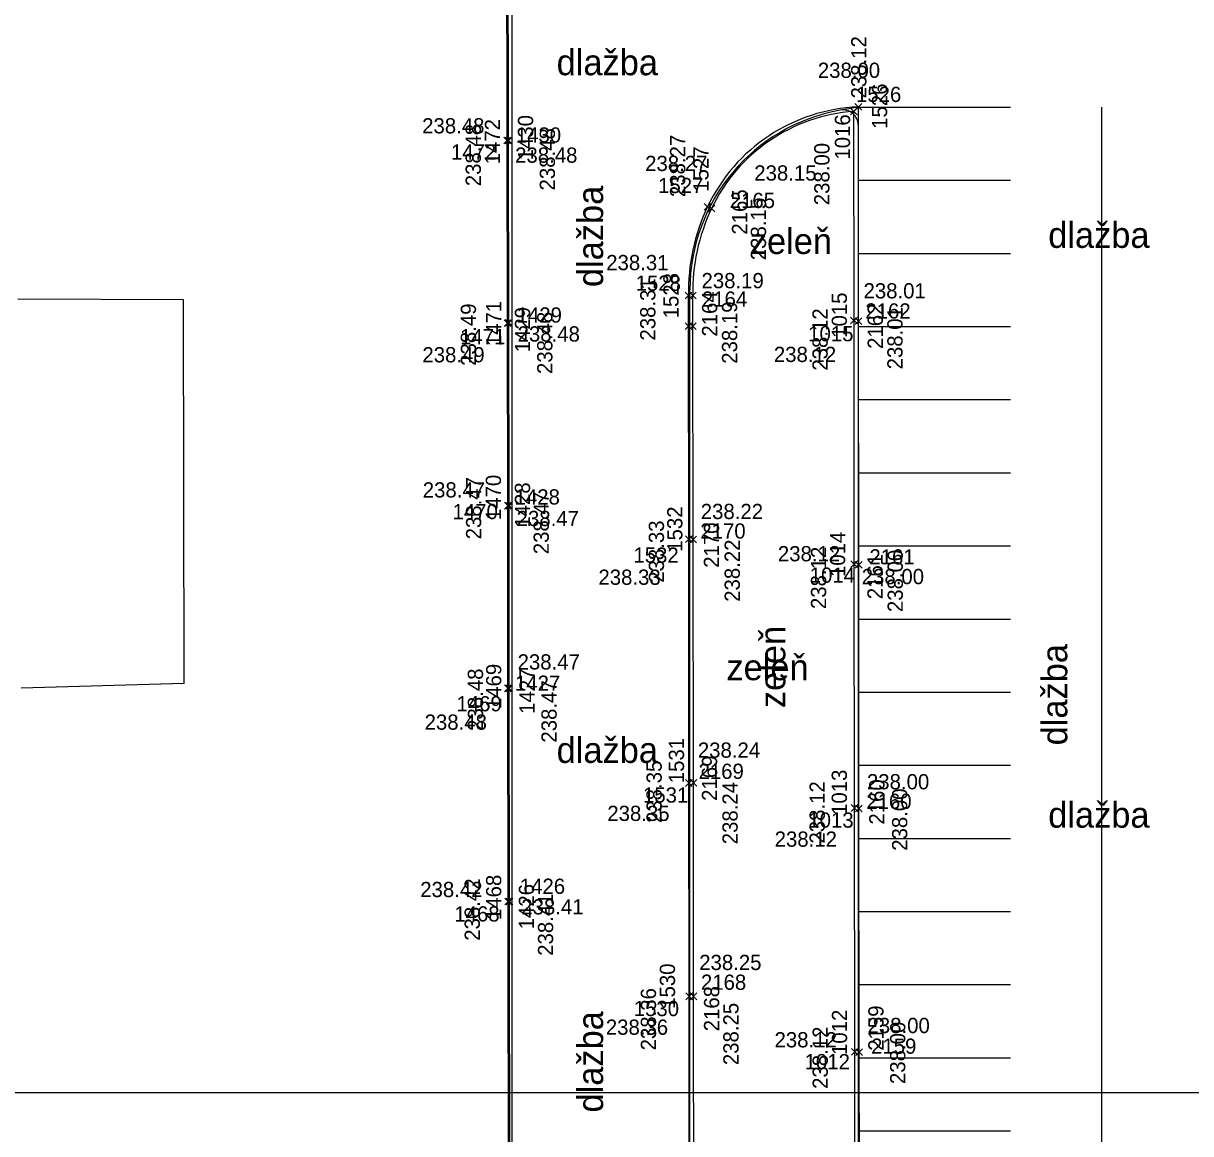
# Model space of a CAD drawing. Extents: x -264205 to -263659, y -1242401 to -1241986.
# Drawn here: x -263975.5 to -263937.18, y -1242121 to -1242084.56 of the extents above; entities that cross this region are included whole.
import ezdxf

# ---------------------------------------------------------------- set-up
doc = ezdxf.new("R2010")
doc.units = 0
for name, color, linetype in [('BOD_CISLO_2-2', 7, 'Continuous'), ('BOD_CISLO_2-3', 7, 'Continuous'), ('BOD_SYMBOL_2-2', 7, 'Continuous'), ('BOD_SYMBOL_2-3', 7, 'Continuous'), ('BOD_VYSKA_2-2', 7, 'Continuous'), ('BOD_VYSKA_2-3', 7, 'Continuous'), ('POPIS_2-2', 7, 'Continuous'), ('POPIS_2-3', 7, 'Continuous'), ('PROJEKT_OBRUBNIKY_KOMUNIKACIE', 7, 'Continuous'), ('PROJEKT_TDZ_VODOROVNE', 7, 'Continuous'), ('RAM_NA_TLAC_2-2_1-250', 7, 'Continuous'), ('SITUACIA_DSP_2D', 7, 'Continuous'), ('SO_20-4_OBRUBNIKY_DOLNA_HRANA', 7, 'Continuous'), ('SO_20-4_OBRUBNIKY_HORNA_HRANA', 7, 'Continuous')]:
    doc.layers.add(name, color=color, linetype=linetype)

msp = doc.modelspace()

# ---------------------------------------------------------------- linework, layer by layer
at = {"layer": 'BOD_SYMBOL_2-2'}
for p, q in [((-263948.198, -1242087.413), (-263947.976, -1242087.191)), ((-263947.976, -1242087.413), (-263948.198, -1242087.191)), ((-263948.198, -1242087.413), (-263947.976, -1242087.191)), ((-263947.976, -1242087.413), (-263948.198, -1242087.191)), ((-263948.345, -1242087.559), (-263948.123, -1242087.338)), ((-263948.123, -1242087.559), (-263948.345, -1242087.338)), ((-263948.345, -1242087.559), (-263948.123, -1242087.338)), ((-263948.123, -1242087.559), (-263948.345, -1242087.338)), ((-263959.726, -1242088.512), (-263959.506, -1242088.291)), ((-263959.506, -1242088.512), (-263959.726, -1242088.291)), ((-263959.68, -1242088.511), (-263959.459, -1242088.289)), ((-263959.459, -1242088.511), (-263959.68, -1242088.289)), ((-263953.148, -1242090.688), (-263952.927, -1242090.468)), ((-263952.927, -1242090.688), (-263953.148, -1242090.468)), ((-263953.019, -1242090.748), (-263952.799, -1242090.526)), ((-263952.799, -1242090.748), (-263953.019, -1242090.526)), ((-263953.775, -1242093.603), (-263953.555, -1242093.382)), ((-263953.555, -1242093.603), (-263953.775, -1242093.382)), ((-263953.632, -1242093.603), (-263953.41, -1242093.382)), ((-263953.41, -1242093.603), (-263953.632, -1242093.382)), ((-263959.715, -1242094.505), (-263959.493, -1242094.284)), ((-263959.493, -1242094.505), (-263959.715, -1242094.284)), ((-263959.669, -1242094.502), (-263959.448, -1242094.282)), ((-263959.448, -1242094.502), (-263959.669, -1242094.282)), ((-263953.775, -1242094.603), (-263953.555, -1242094.382)), ((-263953.555, -1242094.603), (-263953.775, -1242094.382)), ((-263953.629, -1242094.603), (-263953.409, -1242094.383)), ((-263953.409, -1242094.603), (-263953.629, -1242094.383)), ((-263948.34, -1242094.424), (-263948.118, -1242094.204)), ((-263948.118, -1242094.424), (-263948.34, -1242094.204)), ((-263948.193, -1242094.441), (-263947.971, -1242094.221)), ((-263947.971, -1242094.441), (-263948.193, -1242094.221)), ((-263959.707, -1242100.498), (-263959.486, -1242100.278)), ((-263959.486, -1242100.498), (-263959.707, -1242100.278)), ((-263959.66, -1242100.505), (-263959.439, -1242100.284)), ((-263959.439, -1242100.505), (-263959.66, -1242100.284)), ((-263953.766, -1242101.6), (-263953.545, -1242101.38)), ((-263953.545, -1242101.6), (-263953.766, -1242101.38)), ((-263953.62, -1242101.606), (-263953.399, -1242101.384)), ((-263953.399, -1242101.606), (-263953.62, -1242101.384)), ((-263948.334, -1242102.421), (-263948.112, -1242102.2)), ((-263948.112, -1242102.421), (-263948.334, -1242102.2)), ((-263948.187, -1242102.438), (-263947.965, -1242102.217)), ((-263947.965, -1242102.438), (-263948.187, -1242102.217)), ((-263959.707, -1242106.494), (-263959.486, -1242106.272)), ((-263959.486, -1242106.494), (-263959.707, -1242106.272)), ((-263959.66, -1242106.494), (-263959.438, -1242106.272)), ((-263959.438, -1242106.494), (-263959.66, -1242106.272)), ((-263953.761, -1242109.6), (-263953.54, -1242109.379)), ((-263953.54, -1242109.6), (-263953.761, -1242109.379)), ((-263953.614, -1242109.595), (-263953.393, -1242109.373)), ((-263953.393, -1242109.595), (-263953.614, -1242109.373)), ((-263948.324, -1242110.421), (-263948.104, -1242110.2)), ((-263948.104, -1242110.421), (-263948.324, -1242110.2)), ((-263948.177, -1242110.438), (-263947.957, -1242110.217)), ((-263947.957, -1242110.438), (-263948.177, -1242110.217)), ((-263959.697, -1242113.488), (-263959.476, -1242113.268)), ((-263959.476, -1242113.488), (-263959.697, -1242113.268)), ((-263959.649, -1242113.487), (-263959.428, -1242113.265)), ((-263959.428, -1242113.487), (-263959.649, -1242113.265)), ((-263953.756, -1242116.6), (-263953.535, -1242116.38)), ((-263953.535, -1242116.6), (-263953.756, -1242116.38)), ((-263953.609, -1242116.6), (-263953.388, -1242116.38)), ((-263953.388, -1242116.6), (-263953.609, -1242116.38)), ((-263948.317, -1242118.417), (-263948.095, -1242118.197)), ((-263948.095, -1242118.417), (-263948.317, -1242118.197)), ((-263948.17, -1242118.434), (-263947.948, -1242118.214)), ((-263947.948, -1242118.434), (-263948.17, -1242118.214))]:
    msp.add_line(p, q, dxfattribs=at)
at = {"layer": 'BOD_SYMBOL_2-3'}
for p, q in [((-263947.976, -1242087.413), (-263948.198, -1242087.191)), ((-263947.976, -1242087.191), (-263948.198, -1242087.413)), ((-263947.976, -1242087.413), (-263948.198, -1242087.191)), ((-263947.976, -1242087.191), (-263948.198, -1242087.413)), ((-263948.123, -1242087.559), (-263948.345, -1242087.338)), ((-263948.123, -1242087.338), (-263948.345, -1242087.559)), ((-263948.123, -1242087.559), (-263948.345, -1242087.338)), ((-263948.123, -1242087.338), (-263948.345, -1242087.559)), ((-263959.506, -1242088.512), (-263959.726, -1242088.291)), ((-263959.506, -1242088.291), (-263959.726, -1242088.512)), ((-263959.459, -1242088.511), (-263959.68, -1242088.289)), ((-263959.459, -1242088.289), (-263959.68, -1242088.511)), ((-263952.927, -1242090.688), (-263953.148, -1242090.468)), ((-263952.927, -1242090.468), (-263953.148, -1242090.688)), ((-263952.799, -1242090.748), (-263953.019, -1242090.526)), ((-263952.799, -1242090.526), (-263953.019, -1242090.748)), ((-263953.555, -1242093.603), (-263953.775, -1242093.382)), ((-263953.555, -1242093.382), (-263953.775, -1242093.603)), ((-263953.41, -1242093.603), (-263953.632, -1242093.382)), ((-263953.41, -1242093.382), (-263953.632, -1242093.603)), ((-263959.493, -1242094.505), (-263959.715, -1242094.284)), ((-263959.493, -1242094.284), (-263959.715, -1242094.505)), ((-263959.448, -1242094.502), (-263959.669, -1242094.282)), ((-263959.448, -1242094.282), (-263959.669, -1242094.502)), ((-263953.555, -1242094.603), (-263953.775, -1242094.382)), ((-263953.555, -1242094.382), (-263953.775, -1242094.603)), ((-263953.409, -1242094.603), (-263953.629, -1242094.383)), ((-263953.409, -1242094.383), (-263953.629, -1242094.603)), ((-263948.118, -1242094.424), (-263948.34, -1242094.204)), ((-263948.118, -1242094.204), (-263948.34, -1242094.424)), ((-263947.971, -1242094.441), (-263948.193, -1242094.221)), ((-263947.971, -1242094.221), (-263948.193, -1242094.441)), ((-263959.486, -1242100.498), (-263959.707, -1242100.278)), ((-263959.486, -1242100.278), (-263959.707, -1242100.498)), ((-263959.439, -1242100.505), (-263959.66, -1242100.284)), ((-263959.439, -1242100.284), (-263959.66, -1242100.505)), ((-263953.545, -1242101.6), (-263953.766, -1242101.38)), ((-263953.545, -1242101.38), (-263953.766, -1242101.6)), ((-263953.399, -1242101.606), (-263953.62, -1242101.384)), ((-263953.399, -1242101.384), (-263953.62, -1242101.606)), ((-263948.112, -1242102.421), (-263948.334, -1242102.2)), ((-263948.112, -1242102.2), (-263948.334, -1242102.421)), ((-263947.965, -1242102.438), (-263948.187, -1242102.217)), ((-263947.965, -1242102.217), (-263948.187, -1242102.438)), ((-263959.486, -1242106.494), (-263959.707, -1242106.272)), ((-263959.486, -1242106.272), (-263959.707, -1242106.494)), ((-263959.438, -1242106.494), (-263959.66, -1242106.272)), ((-263959.438, -1242106.272), (-263959.66, -1242106.494)), ((-263953.54, -1242109.6), (-263953.761, -1242109.379)), ((-263953.54, -1242109.379), (-263953.761, -1242109.6)), ((-263953.393, -1242109.595), (-263953.614, -1242109.373)), ((-263953.393, -1242109.373), (-263953.614, -1242109.595)), ((-263948.104, -1242110.421), (-263948.324, -1242110.2)), ((-263948.104, -1242110.2), (-263948.324, -1242110.421)), ((-263947.957, -1242110.438), (-263948.177, -1242110.217)), ((-263947.957, -1242110.217), (-263948.177, -1242110.438)), ((-263959.476, -1242113.488), (-263959.697, -1242113.268)), ((-263959.476, -1242113.268), (-263959.697, -1242113.488)), ((-263959.428, -1242113.487), (-263959.649, -1242113.265)), ((-263959.428, -1242113.265), (-263959.649, -1242113.487)), ((-263953.535, -1242116.6), (-263953.756, -1242116.38)), ((-263953.535, -1242116.38), (-263953.756, -1242116.6)), ((-263953.388, -1242116.6), (-263953.609, -1242116.38)), ((-263953.388, -1242116.38), (-263953.609, -1242116.6)), ((-263948.095, -1242118.417), (-263948.317, -1242118.197)), ((-263948.095, -1242118.197), (-263948.317, -1242118.417)), ((-263947.948, -1242118.434), (-263948.17, -1242118.214)), ((-263947.948, -1242118.214), (-263948.17, -1242118.434))]:
    msp.add_line(p, q, dxfattribs=at)
at = {"layer": 'PROJEKT_OBRUBNIKY_KOMUNIKACIE'}
for p, q in [((-263959.468, -1242059.534), (-263959.468, -1242179.482)), ((-263948.093, -1242087.901), (-263948.093, -1242241.458)), ((-263953.617, -1242244.458), (-263953.617, -1242093.307)), ((-263959.468, -1242106.154), (-263959.468, -1242179.482))]:
    msp.add_line(p, q, dxfattribs=at)
for centre, radius, start, end in [((-263947.634, -1242093.3), 5.983, 100.0694, 180.066), ((-263948.593, -1242087.901), 0.5, 0, 100.0694)]:
    msp.add_arc(centre, radius, start, end, dxfattribs=at)
at = {"layer": 'PROJEKT_TDZ_VODOROVNE'}
for p, q in [((-263948.093, -1242087.307), (-263948.593, -1242087.401)), ((-263948.093, -1242087.307), (-263943.093, -1242087.307)), ((-263940.091, -1242134.007), (-263940.093, -1242087.307)), ((-263948.093, -1242089.707), (-263943.093, -1242089.707)), ((-263948.093, -1242092.107), (-263943.093, -1242092.107)), ((-263948.093, -1242094.507), (-263943.093, -1242094.507)), ((-263948.093, -1242096.907), (-263943.093, -1242096.907)), ((-263948.093, -1242099.307), (-263943.093, -1242099.307)), ((-263948.093, -1242101.707), (-263943.093, -1242101.707)), ((-263948.093, -1242104.107), (-263943.093, -1242104.107)), ((-263948.093, -1242106.507), (-263943.093, -1242106.507)), ((-263948.093, -1242108.907), (-263943.093, -1242108.907)), ((-263948.093, -1242111.307), (-263943.093, -1242111.307)), ((-263948.093, -1242113.707), (-263943.093, -1242113.707)), ((-263948.093, -1242116.107), (-263943.093, -1242116.107)), ((-263948.093, -1242118.507), (-263943.093, -1242118.507)), ((-263948.093, -1242120.907), (-263943.093, -1242120.907))]:
    msp.add_line(p, q, dxfattribs=at)
at = {"layer": 'RAM_NA_TLAC_2-2_1-250'}
msp.add_lwpolyline([(-263982.395, -1242045.402), (-263692.395, -1242045.402), (-263692.395, -1242119.652), (-263982.395, -1242119.652)], close=True, dxfattribs=at)
at = {"layer": 'SITUACIA_DSP_2D'}
for p, q in [((-263959.468, -1242059.534), (-263959.468, -1242179.482)), ((-263948.093, -1242087.901), (-263948.093, -1242241.458)), ((-263953.617, -1242244.458), (-263953.617, -1242093.307)), ((-263970.24, -1242093.63), (-263975.68, -1242093.61)), ((-263970.22, -1242106.22), (-263970.24, -1242093.63)), ((-263970.22, -1242106.22), (-263975.57, -1242106.38))]:
    msp.add_line(p, q, dxfattribs=at)
for centre, radius, start, end in [((-263947.634, -1242093.3), 5.983, 100.0694, 180.066), ((-263948.593, -1242087.901), 0.5, 0, 100.0694)]:
    msp.add_arc(centre, radius, start, end, dxfattribs=at)
at = {"layer": 'SO_20-4_OBRUBNIKY_DOLNA_HRANA'}
for points in [[(-263948.011, -1242159.299), (-263948.021, -1242151.313), (-263948.025, -1242142.312), (-263948.033, -1242134.318), (-263948.04, -1242126.323), (-263948.059, -1242118.324), (-263948.067, -1242110.327), (-263948.076, -1242102.327), (-263948.082, -1242094.331), (-263948.087, -1242087.302)], [(-263953.49, -1242123.466), (-263953.498, -1242116.49), (-263953.503, -1242109.484), (-263953.509, -1242101.495), (-263953.519, -1242094.493), (-263953.521, -1242093.492)]]:
    msp.add_lwpolyline(points, dxfattribs=at)
for centre, major_axis, ratio, start_param, end_param in [((-263947.835, -1242093.055), (-3.681, 4.248), 0.999671, 5.64018, 6.695525), ((-263947.162, -1242093.359), (-4.47, -4.528), 0.999533, 5.04879, 5.511915)]:
    msp.add_ellipse(centre, major_axis=major_axis, ratio=ratio, start_param=start_param, end_param=end_param, dxfattribs=at)
at = {"layer": 'SO_20-4_OBRUBNIKY_HORNA_HRANA'}
for points in [[(-263959.578, -1242123.367), (-263959.586, -1242113.378), (-263959.596, -1242106.383), (-263959.596, -1242100.388), (-263959.604, -1242094.394), (-263959.616, -1242088.401), (-263959.627, -1242081.406), (-263959.594, -1242075.406), (-263959.553, -1242068.414)], [(-263959.532, -1242123.37), (-263959.539, -1242113.376), (-263959.549, -1242106.383), (-263959.55, -1242100.394), (-263959.558, -1242094.392), (-263959.569, -1242088.4), (-263959.582, -1242081.402), (-263959.548, -1242075.41), (-263959.506, -1242068.414)], [(-263948.158, -1242159.282), (-263948.168, -1242151.296), (-263948.172, -1242142.295), (-263948.18, -1242134.301), (-263948.187, -1242126.306), (-263948.206, -1242118.307), (-263948.214, -1242110.31), (-263948.223, -1242102.31), (-263948.229, -1242094.314), (-263948.234, -1242087.448)], [(-263953.639, -1242123.464), (-263953.645, -1242116.49), (-263953.65, -1242109.489), (-263953.655, -1242101.49), (-263953.665, -1242094.492), (-263953.665, -1242093.492)]]:
    msp.add_lwpolyline(points, dxfattribs=at)
for centre, major_axis, ratio, start_param, end_param in [((-263947.862, -1242093.02), (-3.734, 4.336), 0.999662, 5.611408, 6.702289), ((-263947.159, -1242093.372), (2.107, -6.159), 0.999591, 3.939244, 4.40131)]:
    msp.add_ellipse(centre, major_axis=major_axis, ratio=ratio, start_param=start_param, end_param=end_param, dxfattribs=at)

# ---------------------------------------------------------------- texts
at = {"layer": 'BOD_CISLO_2-2'}
for s, p in [('1526', (-263948.165, -1242087.14)), ('1430', (-263959.334, -1242088.473)), ('1472', (-263961.462, -1242089.031)), ('1527', (-263954.661, -1242090.131)), ('2165', (-263952.31, -1242090.62)), ('1528', (-263955.399, -1242093.336)), ('2164', (-263953.224, -1242093.858)), ('2162', (-263947.858, -1242094.248)), ('1429', (-263959.307, -1242094.38)), ('1015', (-263949.734, -1242094.993)), ('1471', (-263961.166, -1242095.093)), ('1428', (-263959.373, -1242100.35)), ('1470', (-263961.41, -1242100.831)), ('2170', (-263953.275, -1242101.469)), ('1532', (-263955.472, -1242102.26)), ('2161', (-263947.725, -1242102.318)), ('1014', (-263949.684, -1242102.917)), ('1427', (-263959.362, -1242106.464)), ('1469', (-263961.281, -1242107.137)), ('2169', (-263953.334, -1242109.355)), ('1531', (-263955.157, -1242110.133)), ('2160', (-263947.827, -1242110.34)), ('1013', (-263949.729, -1242110.955)), ('1426', (-263959.202, -1242113.128)), ('1468', (-263961.352, -1242114.035)), ('2168', (-263953.255, -1242116.277)), ('1530', (-263955.461, -1242117.139)), ('2159', (-263947.669, -1242118.376)), ('1012', (-263949.851, -1242118.884))]:
    msp.add_text(s, height=0.5, dxfattribs=at).set_placement(p)
at = {"layer": 'BOD_CISLO_2-3'}
for s, p in [('1526', (-263947.141, -1242088.021)), ('1430', (-263958.764, -1242089.056)), ('1016', (-263948.359, -1242089.031)), ('1472', (-263959.85, -1242089.187)), ('1527', (-263953.006, -1242090.086)), ('2165', (-263951.737, -1242091.493)), ('1528', (-263953.989, -1242094.239)), ('2164', (-263952.72, -1242094.84)), ('1015', (-263948.462, -1242094.879)), ('1471', (-263959.807, -1242095.154)), ('2162', (-263947.283, -1242095.242)), ('1429', (-263958.863, -1242095.355)), ('1470', (-263959.82, -1242100.862)), ('1428', (-263958.865, -1242101.111)), ('1532', (-263953.863, -1242101.901)), ('2170', (-263952.66, -1242102.427)), ('1014', (-263948.52, -1242102.729)), ('2161', (-263947.291, -1242103.457)), ('1469', (-263959.809, -1242107.065)), ('1427', (-263958.716, -1242107.221)), ('1531', (-263953.81, -1242109.496)), ('2169', (-263952.724, -1242110.076)), ('1013', (-263948.463, -1242110.538)), ('2160', (-263947.231, -1242110.855)), ('1468', (-263959.81, -1242113.987)), ('1426', (-263958.735, -1242114.292)), ('1530', (-263954.106, -1242116.9)), ('2168', (-263952.655, -1242117.638)), ('1012', (-263948.456, -1242118.416)), ('2159', (-263947.261, -1242118.278))]:
    msp.add_text(s, height=0.5, rotation=90, dxfattribs=at).set_placement(p)
at = {"layer": 'BOD_VYSKA_2-2'}
for s, p in [('238.00', (-263949.418, -1242086.349)), ('238.48', (-263962.408, -1242088.171)), ('238.48', (-263959.355, -1242089.133)), ('238.27', (-263955.087, -1242089.406)), ('238.15', (-263951.504, -1242089.719)), ('238.31', (-263956.365, -1242092.66)), ('238.19', (-263953.236, -1242093.252)), ('238.01', (-263947.917, -1242093.586)), ('238.48', (-263959.274, -1242095.002)), ('238.49', (-263962.4, -1242095.684)), ('238.12', (-263950.861, -1242095.673)), ('238.47', (-263962.388, -1242100.12)), ('238.22', (-263953.261, -1242100.828)), ('238.47', (-263959.305, -1242101.058)), ('238.12', (-263950.729, -1242102.214)), ('238.33', (-263956.621, -1242102.985)), ('238.00', (-263947.976, -1242102.964)), ('238.47', (-263959.274, -1242105.765)), ('238.48', (-263962.327, -1242107.741)), ('238.24', (-263953.357, -1242108.66)), ('238.00', (-263947.805, -1242109.697)), ('238.35', (-263956.329, -1242110.735)), ('238.12', (-263950.835, -1242111.581)), ('238.42', (-263962.471, -1242113.234)), ('238.41', (-263959.153, -1242113.802)), ('238.25', (-263953.312, -1242115.628)), ('238.00', (-263947.786, -1242117.697)), ('238.36', (-263956.378, -1242117.752)), ('238.12', (-263950.839, -1242118.166))]:
    msp.add_text(s, height=0.5, dxfattribs=at).set_placement(p)
at = {"layer": 'BOD_VYSKA_2-3'}
for s, p in [('238.12', (-263947.823, -1242087.024)), ('238.48', (-263960.481, -1242089.904)), ('238.48', (-263958.048, -1242090.044)), ('238.27', (-263953.771, -1242090.261)), ('238.00', (-263949.036, -1242090.528)), ('238.15', (-263951.118, -1242092.332)), ('238.31', (-263954.75, -1242094.969)), ('238.49', (-263960.639, -1242095.797)), ('238.19', (-263952.065, -1242095.731)), ('238.48', (-263958.131, -1242096.067)), ('238.12', (-263949.095, -1242095.957)), ('238.01', (-263946.636, -1242095.915)), ('238.47', (-263960.468, -1242101.493)), ('238.47', (-263958.249, -1242101.981)), ('238.33', (-263954.468, -1242102.919)), ('238.22', (-263951.978, -1242103.543)), ('238.12', (-263949.144, -1242103.781)), ('238.00', (-263946.627, -1242103.88)), ('238.48', (-263960.409, -1242107.777)), ('238.47', (-263957.992, -1242108.164)), ('238.35', (-263954.543, -1242110.801)), ('238.24', (-263952.05, -1242111.5)), ('238.12', (-263949.189, -1242111.477)), ('238.00', (-263946.481, -1242111.714)), ('238.42', (-263960.513, -1242114.667)), ('238.41', (-263958.107, -1242115.161)), ('238.36', (-263954.73, -1242118.264)), ('238.25', (-263952.021, -1242118.749)), ('238.12', (-263949.09, -1242119.528)), ('238.00', (-263946.546, -1242119.369))]:
    msp.add_text(s, height=0.5, rotation=90, dxfattribs=at).set_placement(p)
at = {"layer": 'POPIS_2-2'}
for s, p in [('dlažba', (-263957.992, -1242086.261)), ('dlažba', (-263941.853, -1242091.927)), ('zeleň', (-263951.651, -1242092.129)), ('zeleň', (-263952.419, -1242106.115)), ('dlažba', (-263957.992, -1242108.83)), ('dlažba', (-263941.853, -1242110.955))]:
    msp.add_text(s, height=0.8438, dxfattribs=at).set_placement(p)
at = {"layer": 'POPIS_2-3'}
for s, p in [('dlažba', (-263956.467, -1242093.214)), ('zeleň', (-263950.485, -1242107.032)), ('dlažba', (-263941.228, -1242108.254)), ('dlažba', (-263956.467, -1242120.303))]:
    msp.add_text(s, height=0.8438, rotation=90, dxfattribs=at).set_placement(p)

doc.saveas('drawing.dxf')
